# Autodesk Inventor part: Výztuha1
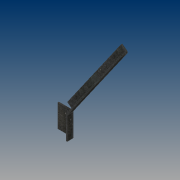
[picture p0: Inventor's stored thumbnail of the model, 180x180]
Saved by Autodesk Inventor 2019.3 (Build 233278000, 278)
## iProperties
Created: 2019-02
Part Number: Výztuha1
Material: Ocel, měkká, svařovaná
Document SubType Name: Plech
Designer: B-hon
Density: 7.85 g/cm^3
Sheet Metal Rule: Výchozí_mm
Appearance: Plech
Author: B-hon
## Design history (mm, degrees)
node "Plocha1"
  sketch "Náčrt1"
    geometry: L1 (-7, 0)-(-48, 0); L2 (-48, 0)-(-48, 310); L3 (-7, 310)-(-7, 0); L4 (-48, 310)-(-7, 310); 5 further points
    constraints: 8 end point, 2 horizontal alignment, 1 horizontal, 1 parallel, 1 perpendicular
    dimensions: "d5" = 7 vertical distance of point (0, 0) point (-17, 7); "d6" = 17 horizontal distance of point (0, 0) point (-17, 7); "d7" = 21 distance of point (-38, 7) point (-17, 7); "d8" = 45 vertical distance of point (-17, 7) point (-27.5, 52); "d9" = 10.5 horizontal distance of point (-17, 7) point (-27.5, 52) (= 0.5 x d7); "d10" = 10 distance from line of point (-17, 7) L3; "d11" = 10 distance from line of point (-38, 7) L2 (= d10); "d12" = 250 distance from line of L3 point (243, 370); "d13" = 370 distance from line of L1 point (243, 370); "d15" = 310 distance of L1.end L2.end
node "Obruba3"
sketch "Náčrt5"
  geometry: L1 (-28.904, 62)-(-14, 62); L2 (-14, 62)-(-14, 60); L3 (-14, 60)-(-28.904, 60); L4 (-28.904, 60)-(-28.904, 62); L5 (-14, 0)-(0, 0) reference; L6 (-14, 310)-(-14, 0) reference; 1 further point
  constraints: 8 end point, 2 parallel, 1 horizontal, 1 perpendicular
  dimensions: "d50" = 60 distance between parallel lines of L5 L3; "d51" = 2 distance of L1.end L2.end; "d52" = 0 distance between parallel lines of L6 L2
extrude "Vysunutí1" cut sketch "Náčrt5" stored distance "d53" = 200; taper "d54" = 0 deg
node "Upravit přímo1"
sketch "Náčrt6"
  geometry: L1 (-9.893, 60)-(57.958, 60); L2 (17, 60)-(20, 60) reference; 1 further point
  constraints: 2 end point, 1 collinear
  dimensions: "d58" = 0 distance between parallel lines of L1 L2
feature "Ohyb součásti1" sketch "Náčrt6" dims "d59" = 3, "d60" = 35 deg
sketch "Náčrt7"
  geometry: L1 (13, 0)-(48, 0) reference; 4 further points
  constraints: 1 horizontal alignment
  dimensions: "d61" = 7 distance from line of L1 point (21, 7); "d62" = 21 horizontal distance of point (0, 0) point (21, 7); "d63" = 21 distance of point (42, 7) point (21, 7); "d64" = 10.5 horizontal distance of point (42, 7) point (31.5, 52) (= 0.5 x d63); "d65" = 45 vertical distance of point (42, 7) point (31.5, 52)
hole "Díra1" sketch "Náčrt7" at (21, 7), (42, 7), (31.5, 52) diameter "d66" = 5.5; stored, may be unused: countersink angle "d70" = 90 deg, drill point angle "d72" = 0 deg; dims "d67" = 6, "d68" = 4, "d69" = 2, "d71" = 3 (= Tloušťka)
node "Upravit přímo2"
node "Těleso1"
feature "Deska1" dims "d14" = 3 (= Tloušťka)
sketch "Náčrt4"
  geometry: L1 through (-155, 0) direction (1, 0); L2 through (0, 10) direction (-3.42e-32, 1); L3 (0, 20)-(-310, 20); L4 (-310, 20)-(-310, 0)
  constraints: 6 end point, 1 horizontal, 1 perpendicular, 1 vertical
feature "Deska4" dims "d14" = 3 (= Tloušťka), "d40" = 3 (= ŠířkaVýštipu), "d41" = 1.5 (= HloubkaVýštipu), "d42" = 6 (= MinimálníZbytek), "d43" = 3 (= PřechodovýPoloměr), "d44" = 20, "d45" = 90 deg, "d46" = 3 (= PoloměrOhybu), "d47" = 12 (= VelikostRohovéhoVýštipu), "d48" = 3 (= VelikostMezery), "d49" = 3 (= VelikostJacobihoPoloměru), "MezeraVystřižení" = 0.01
feature "Ohyb3" dims "d14" = 3 (= Tloušťka), "d40" = 3 (= ŠířkaVýštipu), "d41" = 1.5 (= HloubkaVýštipu), "d42" = 6 (= MinimálníZbytek), "d43" = 3 (= PřechodovýPoloměr), "d44" = 20, "d45" = 90 deg, "d46" = 3 (= PoloměrOhybu), "MezeraVystřižení" = 0.01
feature "Roh3" dims "d44" = 20, "d45" = 90 deg, "d47" = 12 (= VelikostRohovéhoVýštipu), "d48" = 3 (= VelikostMezery), "d49" = 3 (= VelikostJacobihoPoloměru)
feature "Posunout1" dims "d57" = -20
feature "Posunout2" dims "d75" = 1
other parameters: "Tloušťka" = 3 (derived), "KSoučinitel" = 4.4, "PoloměrOhybu" = 3 (= Tloušťka), "ŠířkaVýštipu" = 3 (= Tloušťka), "HloubkaVýštipu" = 1.5 (= 0.5 x Tloušťka), "VelikostRohovéhoVýštipu" = 12 (= 4 x Tloušťka), "MinimálníZbytek" = 6 (= 2 x Tloušťka), "PřechodovýPoloměr" = 3 (= PoloměrOhybu), "VelikostJacobihoPoloměru" = 3 (= PoloměrOhybu), "VelikostMezery" = 3 (= Tloušťka), "d55" = 0, "d56" = 0, "d73" = 0, "d74" = 0
